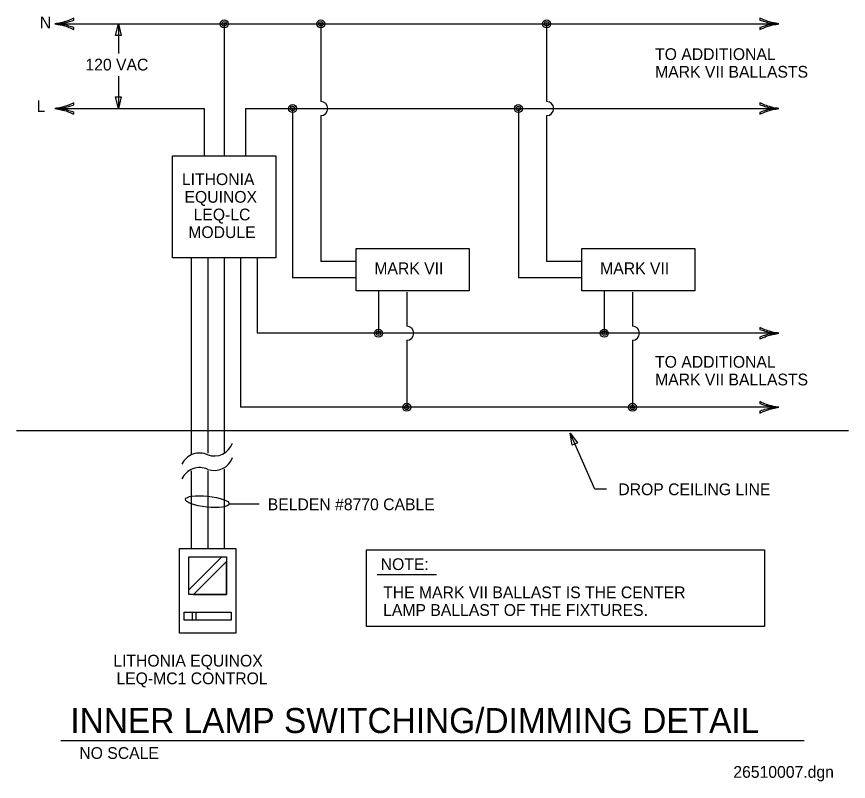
# Model space of a CAD drawing. Extents: x 10215.2 to 10262.3, y 10050.3 to 10093.6.
import ezdxf

# ---------------------------------------------------------------- set-up
doc = ezdxf.new("R2010")
doc.units = 0
for name, color, linetype in [('G-ANNO-TEXT', 7, 'Continuous'), ('G-DETL-OTLN', 7, 'Continuous'), ('Level 61', 7, 'Continuous')]:
    doc.layers.add(name, color=color, linetype=linetype)

msp = doc.modelspace()

# ---------------------------------------------------------------- linework, layer by layer
at = {"layer": 'G-ANNO-TEXT'}
for p, q in [((10220.937, 10093.182), (10220.937, 10091.493)), ((10220.937, 10090.216), (10220.937, 10088.382)), ((10247.945, 10066.804), (10246.539, 10069.988)), ((10248.612, 10066.804), (10247.945, 10066.804)), ((10227.223, 10065.974), (10228.928, 10065.974)), ((10235.608, 10061.97), (10238.975, 10061.97)), ((10217.675, 10052.56), (10259.814, 10052.56))]:
    msp.add_line(p, q, dxfattribs=at)
for points in [[(10220.77, 10092.515), (10220.937, 10093.182), (10221.103, 10092.515)], [(10221.103, 10089.048), (10220.937, 10088.382), (10220.77, 10089.048)], [(10246.656, 10069.311), (10246.539, 10069.988), (10246.961, 10069.445)], [(10235.008, 10063.37), (10257.557, 10063.37), (10257.557, 10059.023), (10235.008, 10059.023)]]:
    msp.add_lwpolyline(points, close=True, dxfattribs=at)
msp.add_ellipse((10225.98, 10066.106), major_axis=(1.243, -0.132), ratio=0.246355, dxfattribs=at)
at = {"layer": 'G-DETL-OTLN'}
for p, q in [((10217.337, 10093.182), (10258.385, 10093.182)), ((10226.937, 10093.182), (10226.937, 10085.706)), ((10232.414, 10093.182), (10232.414, 10088.782)), ((10245.214, 10093.182), (10245.214, 10088.782)), ((10217.337, 10088.382), (10225.803, 10088.382)), ((10225.803, 10088.382), (10225.803, 10085.706)), ((10228.137, 10088.382), (10258.385, 10088.382)), ((10228.137, 10088.382), (10228.137, 10085.706)), ((10230.814, 10088.382), (10230.814, 10078.782)), ((10243.614, 10088.382), (10243.614, 10078.782)), ((10232.414, 10087.982), (10232.414, 10079.715)), ((10245.214, 10087.982), (10245.214, 10079.715)), ((10225.07, 10079.924), (10225.07, 10068.818)), ((10226.003, 10079.924), (10226.003, 10068.86)), ((10226.937, 10079.924), (10226.937, 10068.86)), ((10227.87, 10079.924), (10227.87, 10071.45)), ((10228.803, 10079.924), (10228.803, 10075.648)), ((10234.414, 10079.715), (10232.414, 10079.715)), ((10247.214, 10079.715), (10245.214, 10079.715)), ((10234.414, 10078.782), (10230.814, 10078.782)), ((10247.214, 10078.782), (10243.614, 10078.782)), ((10235.681, 10078.048), (10235.681, 10075.648)), ((10237.281, 10077.982), (10237.281, 10076.048)), ((10248.481, 10078.048), (10248.481, 10075.648)), ((10250.081, 10077.982), (10250.081, 10076.048)), ((10258.385, 10075.648), (10228.803, 10075.648)), ((10237.281, 10075.248), (10237.281, 10071.45)), ((10250.081, 10075.248), (10250.081, 10071.45)), ((10258.385, 10071.45), (10227.87, 10071.45)), ((10225.07, 10067.848), (10225.07, 10063.448)), ((10226.003, 10067.848), (10226.003, 10063.448)), ((10226.937, 10067.943), (10226.937, 10063.448)), ((10224.937, 10061.115), (10224.937, 10062.982)), ((10224.937, 10062.982), (10226.803, 10062.982)), ((10227.07, 10060.848), (10227.07, 10062.715)), ((10225.203, 10060.848), (10227.07, 10060.848))]:
    msp.add_line(p, q, dxfattribs=at)
for points in [[(10217.337, 10093.182), (10217.431, 10093.166), (10217.524, 10093.151), (10217.645, 10093.132), (10217.77, 10093.098), (10217.877, 10093.07), (10217.97, 10093.044), (10218.047, 10093.014), (10218.132, 10092.982), (10218.21, 10092.951), (10218.29, 10092.919), (10218.361, 10092.886), (10218.417, 10092.858), (10218.417, 10092.966), (10218.348, 10092.991), (10218.281, 10093.015), (10218.209, 10093.036), (10218.138, 10093.057), (10218.05, 10093.081), (10217.981, 10093.102), (10217.885, 10093.119), (10217.804, 10093.134), (10217.711, 10093.15), (10217.625, 10093.161), (10217.546, 10093.167), (10217.482, 10093.172), (10217.417, 10093.177), (10217.337, 10093.182), (10217.437, 10093.188), (10217.537, 10093.196), (10217.666, 10093.206), (10217.785, 10093.226), (10217.873, 10093.242), (10217.964, 10093.258), (10218.05, 10093.281), (10218.161, 10093.313), (10218.239, 10093.335), (10218.321, 10093.362), (10218.417, 10093.398), (10218.417, 10093.506), (10218.345, 10093.471), (10218.241, 10093.423), (10218.162, 10093.394), (10218.06, 10093.354), (10217.957, 10093.316), (10217.871, 10093.292), (10217.764, 10093.263), (10217.685, 10093.241), (10217.599, 10093.225), (10217.513, 10093.21), (10217.425, 10093.196), (10217.337, 10093.182)], [(10217.337, 10093.182), (10217.431, 10093.166), (10217.524, 10093.151), (10217.645, 10093.132), (10217.77, 10093.098), (10217.877, 10093.07), (10217.97, 10093.044), (10218.047, 10093.014), (10218.132, 10092.982), (10218.21, 10092.951), (10218.29, 10092.919), (10218.361, 10092.886), (10218.417, 10092.858), (10218.417, 10092.966), (10218.348, 10092.991), (10218.281, 10093.015), (10218.209, 10093.036), (10218.138, 10093.057), (10218.05, 10093.081), (10217.981, 10093.102), (10217.885, 10093.119), (10217.804, 10093.134), (10217.711, 10093.15), (10217.625, 10093.161), (10217.546, 10093.167), (10217.482, 10093.172), (10217.417, 10093.177), (10217.337, 10093.182), (10217.437, 10093.188), (10217.537, 10093.196), (10217.666, 10093.206), (10217.785, 10093.226), (10217.873, 10093.242), (10217.964, 10093.258), (10218.05, 10093.281), (10218.161, 10093.313), (10218.239, 10093.335), (10218.321, 10093.362), (10218.417, 10093.398), (10218.417, 10093.506), (10218.345, 10093.471), (10218.241, 10093.423), (10218.162, 10093.394), (10218.06, 10093.354), (10217.957, 10093.316), (10217.871, 10093.292), (10217.764, 10093.263), (10217.685, 10093.241), (10217.599, 10093.225), (10217.513, 10093.21), (10217.425, 10093.196), (10217.337, 10093.182)], [(10258.385, 10093.182), (10258.291, 10093.198), (10258.198, 10093.212), (10258.076, 10093.231), (10257.951, 10093.265), (10257.844, 10093.294), (10257.751, 10093.319), (10257.675, 10093.35), (10257.59, 10093.382), (10257.511, 10093.412), (10257.431, 10093.444), (10257.361, 10093.478), (10257.305, 10093.505), (10257.305, 10093.398), (10257.374, 10093.372), (10257.441, 10093.348), (10257.513, 10093.327), (10257.583, 10093.306), (10257.671, 10093.282), (10257.74, 10093.262), (10257.836, 10093.244), (10257.918, 10093.23), (10258.011, 10093.214), (10258.097, 10093.202), (10258.175, 10093.196), (10258.239, 10093.191), (10258.305, 10093.186), (10258.385, 10093.182), (10258.284, 10093.175), (10258.185, 10093.167), (10258.055, 10093.158), (10257.937, 10093.137), (10257.849, 10093.121), (10257.758, 10093.105), (10257.671, 10093.082), (10257.561, 10093.05), (10257.483, 10093.028), (10257.401, 10093.001), (10257.305, 10092.966), (10257.305, 10092.857), (10257.377, 10092.892), (10257.481, 10092.94), (10257.559, 10092.969), (10257.662, 10093.009), (10257.764, 10093.047), (10257.851, 10093.071), (10257.958, 10093.1), (10258.036, 10093.122), (10258.123, 10093.138), (10258.209, 10093.153), (10258.297, 10093.167), (10258.385, 10093.182)], [(10217.337, 10088.382), (10217.431, 10088.366), (10217.524, 10088.351), (10217.645, 10088.332), (10217.77, 10088.298), (10217.877, 10088.27), (10217.97, 10088.244), (10218.047, 10088.214), (10218.132, 10088.182), (10218.21, 10088.151), (10218.29, 10088.119), (10218.361, 10088.086), (10218.417, 10088.058), (10218.417, 10088.166), (10218.348, 10088.191), (10218.281, 10088.215), (10218.209, 10088.236), (10218.138, 10088.257), (10218.05, 10088.281), (10217.981, 10088.302), (10217.885, 10088.319), (10217.804, 10088.334), (10217.711, 10088.35), (10217.625, 10088.361), (10217.546, 10088.367), (10217.482, 10088.372), (10217.417, 10088.377), (10217.337, 10088.382), (10217.437, 10088.388), (10217.537, 10088.396), (10217.666, 10088.406), (10217.785, 10088.426), (10217.873, 10088.442), (10217.964, 10088.458), (10218.05, 10088.481), (10218.161, 10088.513), (10218.239, 10088.535), (10218.321, 10088.562), (10218.417, 10088.598), (10218.417, 10088.706), (10218.345, 10088.671), (10218.241, 10088.623), (10218.162, 10088.594), (10218.06, 10088.554), (10217.957, 10088.516), (10217.871, 10088.492), (10217.764, 10088.463), (10217.685, 10088.441), (10217.599, 10088.425), (10217.513, 10088.41), (10217.425, 10088.396), (10217.337, 10088.382)], [(10217.337, 10088.382), (10217.431, 10088.366), (10217.524, 10088.351), (10217.645, 10088.332), (10217.77, 10088.298), (10217.877, 10088.27), (10217.97, 10088.244), (10218.047, 10088.214), (10218.132, 10088.182), (10218.21, 10088.151), (10218.29, 10088.119), (10218.361, 10088.086), (10218.417, 10088.058), (10218.417, 10088.166), (10218.348, 10088.191), (10218.281, 10088.215), (10218.209, 10088.236), (10218.138, 10088.257), (10218.05, 10088.281), (10217.981, 10088.302), (10217.885, 10088.319), (10217.804, 10088.334), (10217.711, 10088.35), (10217.625, 10088.361), (10217.546, 10088.367), (10217.482, 10088.372), (10217.417, 10088.377), (10217.337, 10088.382), (10217.437, 10088.388), (10217.537, 10088.396), (10217.666, 10088.406), (10217.785, 10088.426), (10217.873, 10088.442), (10217.964, 10088.458), (10218.05, 10088.481), (10218.161, 10088.513), (10218.239, 10088.535), (10218.321, 10088.562), (10218.417, 10088.598), (10218.417, 10088.706), (10218.345, 10088.671), (10218.241, 10088.623), (10218.162, 10088.594), (10218.06, 10088.554), (10217.957, 10088.516), (10217.871, 10088.492), (10217.764, 10088.463), (10217.685, 10088.441), (10217.599, 10088.425), (10217.513, 10088.41), (10217.425, 10088.396), (10217.337, 10088.382)], [(10258.385, 10088.382), (10258.291, 10088.398), (10258.198, 10088.412), (10258.076, 10088.431), (10257.951, 10088.465), (10257.844, 10088.494), (10257.751, 10088.519), (10257.675, 10088.55), (10257.59, 10088.582), (10257.511, 10088.612), (10257.431, 10088.644), (10257.361, 10088.678), (10257.305, 10088.705), (10257.305, 10088.598), (10257.374, 10088.572), (10257.441, 10088.548), (10257.513, 10088.527), (10257.583, 10088.506), (10257.671, 10088.482), (10257.74, 10088.462), (10257.836, 10088.444), (10257.918, 10088.43), (10258.011, 10088.414), (10258.097, 10088.402), (10258.175, 10088.396), (10258.239, 10088.391), (10258.305, 10088.386), (10258.385, 10088.382), (10258.284, 10088.375), (10258.185, 10088.367), (10258.055, 10088.358), (10257.937, 10088.337), (10257.849, 10088.321), (10257.758, 10088.305), (10257.671, 10088.282), (10257.561, 10088.25), (10257.483, 10088.228), (10257.401, 10088.201), (10257.305, 10088.166), (10257.305, 10088.057), (10257.377, 10088.092), (10257.481, 10088.14), (10257.559, 10088.169), (10257.662, 10088.209), (10257.764, 10088.247), (10257.851, 10088.271), (10257.958, 10088.3), (10258.036, 10088.322), (10258.123, 10088.338), (10258.209, 10088.353), (10258.297, 10088.367), (10258.385, 10088.382)], [(10258.385, 10075.648), (10258.291, 10075.664), (10258.198, 10075.679), (10258.076, 10075.698), (10257.951, 10075.731), (10257.844, 10075.76), (10257.751, 10075.786), (10257.675, 10075.816), (10257.59, 10075.848), (10257.511, 10075.879), (10257.431, 10075.911), (10257.361, 10075.944), (10257.305, 10075.971), (10257.305, 10075.864), (10257.374, 10075.839), (10257.441, 10075.815), (10257.513, 10075.794), (10257.583, 10075.773), (10257.671, 10075.749), (10257.74, 10075.728), (10257.836, 10075.711), (10257.918, 10075.696), (10258.011, 10075.68), (10258.097, 10075.669), (10258.175, 10075.663), (10258.239, 10075.658), (10258.305, 10075.653), (10258.385, 10075.648), (10258.284, 10075.642), (10258.185, 10075.634), (10258.055, 10075.624), (10257.937, 10075.603), (10257.849, 10075.587), (10257.758, 10075.571), (10257.671, 10075.549), (10257.561, 10075.517), (10257.483, 10075.495), (10257.401, 10075.467), (10257.305, 10075.432), (10257.305, 10075.323), (10257.377, 10075.359), (10257.481, 10075.407), (10257.559, 10075.435), (10257.662, 10075.475), (10257.764, 10075.514), (10257.851, 10075.538), (10257.958, 10075.567), (10258.036, 10075.589), (10258.123, 10075.605), (10258.209, 10075.619), (10258.297, 10075.634), (10258.385, 10075.648)], [(10258.385, 10075.648), (10258.291, 10075.664), (10258.198, 10075.679), (10258.076, 10075.698), (10257.951, 10075.731), (10257.844, 10075.76), (10257.751, 10075.786), (10257.675, 10075.816), (10257.59, 10075.848), (10257.511, 10075.879), (10257.431, 10075.911), (10257.361, 10075.944), (10257.305, 10075.971), (10257.305, 10075.864), (10257.374, 10075.839), (10257.441, 10075.815), (10257.513, 10075.794), (10257.583, 10075.773), (10257.671, 10075.749), (10257.74, 10075.728), (10257.836, 10075.711), (10257.918, 10075.696), (10258.011, 10075.68), (10258.097, 10075.669), (10258.175, 10075.663), (10258.239, 10075.658), (10258.305, 10075.653), (10258.385, 10075.648), (10258.284, 10075.642), (10258.185, 10075.634), (10258.055, 10075.624), (10257.937, 10075.603), (10257.849, 10075.587), (10257.758, 10075.571), (10257.671, 10075.549), (10257.561, 10075.517), (10257.483, 10075.495), (10257.401, 10075.467), (10257.305, 10075.432), (10257.305, 10075.323), (10257.377, 10075.359), (10257.481, 10075.407), (10257.559, 10075.435), (10257.662, 10075.475), (10257.764, 10075.514), (10257.851, 10075.538), (10257.958, 10075.567), (10258.036, 10075.589), (10258.123, 10075.605), (10258.209, 10075.619), (10258.297, 10075.634), (10258.385, 10075.648)], [(10258.385, 10071.45), (10258.291, 10071.466), (10258.198, 10071.481), (10258.076, 10071.5), (10257.951, 10071.533), (10257.844, 10071.562), (10257.751, 10071.588), (10257.675, 10071.618), (10257.59, 10071.65), (10257.511, 10071.681), (10257.431, 10071.713), (10257.361, 10071.746), (10257.305, 10071.773), (10257.305, 10071.666), (10257.374, 10071.641), (10257.441, 10071.617), (10257.513, 10071.596), (10257.583, 10071.575), (10257.671, 10071.551), (10257.74, 10071.53), (10257.836, 10071.513), (10257.918, 10071.498), (10258.011, 10071.482), (10258.097, 10071.471), (10258.175, 10071.465), (10258.239, 10071.46), (10258.305, 10071.455), (10258.385, 10071.45), (10258.284, 10071.444), (10258.185, 10071.436), (10258.055, 10071.426), (10257.937, 10071.405), (10257.849, 10071.389), (10257.758, 10071.373), (10257.671, 10071.351), (10257.561, 10071.319), (10257.483, 10071.297), (10257.401, 10071.269), (10257.305, 10071.234), (10257.305, 10071.125), (10257.377, 10071.161), (10257.481, 10071.209), (10257.559, 10071.237), (10257.662, 10071.277), (10257.764, 10071.316), (10257.851, 10071.34), (10257.958, 10071.369), (10258.036, 10071.391), (10258.123, 10071.407), (10258.209, 10071.421), (10258.297, 10071.436), (10258.385, 10071.45)]]:
    msp.add_lwpolyline(points, dxfattribs=at)
for points in [[(10224.012, 10085.706), (10229.861, 10085.706), (10229.861, 10079.924), (10224.012, 10079.924)], [(10234.414, 10080.448), (10240.814, 10080.448), (10240.814, 10078.048), (10234.414, 10078.048)], [(10247.214, 10080.448), (10253.614, 10080.448), (10253.614, 10078.048), (10247.214, 10078.048)], [(10224.403, 10063.448), (10227.603, 10063.448), (10227.603, 10058.648), (10224.403, 10058.648)], [(10224.937, 10062.982), (10227.07, 10062.982), (10227.07, 10060.848), (10224.937, 10060.848)], [(10224.67, 10059.848), (10227.337, 10059.848), (10227.337, 10059.382), (10224.67, 10059.382)]]:
    msp.add_lwpolyline(points, close=True, dxfattribs=at)
for centre, radius in [((10226.937, 10093.182), 0.226), ((10226.937, 10093.182), 0.127), ((10226.937, 10093.182), 0.0422), ((10232.414, 10093.182), 0.226), ((10232.414, 10093.182), 0.127), ((10232.414, 10093.182), 0.0422), ((10245.214, 10093.182), 0.226), ((10245.214, 10093.182), 0.127), ((10245.214, 10093.182), 0.0422), ((10230.814, 10088.382), 0.226), ((10230.814, 10088.382), 0.127), ((10230.814, 10088.382), 0.0422), ((10243.614, 10088.382), 0.226), ((10243.614, 10088.382), 0.127), ((10243.614, 10088.382), 0.0422), ((10235.681, 10075.648), 0.226), ((10235.681, 10075.648), 0.127), ((10235.681, 10075.648), 0.0422), ((10248.481, 10075.648), 0.226), ((10248.481, 10075.648), 0.127), ((10248.481, 10075.648), 0.0422), ((10237.281, 10071.45), 0.226), ((10237.281, 10071.45), 0.127), ((10237.281, 10071.45), 0.0422), ((10250.081, 10071.45), 0.226), ((10250.081, 10071.45), 0.127), ((10250.081, 10071.45), 0.0422)]:
    msp.add_circle(centre, radius, dxfattribs=at)
for centre in [(10232.414, 10088.382), (10245.214, 10088.382), (10237.281, 10075.648), (10250.081, 10075.648)]:
    msp.add_arc(centre, 0.4, 270, 90, dxfattribs=at)
at = {"layer": 'Level 61'}
for p, q in [((10262.317, 10070.117), (10215.171, 10070.117)), ((10224.937, 10061.115), (10226.803, 10062.982)), ((10226.803, 10062.982), (10224.937, 10061.115)), ((10225.203, 10060.848), (10227.07, 10062.715)), ((10227.07, 10062.715), (10225.203, 10060.848))]:
    msp.add_line(p, q, dxfattribs=at)
msp.add_lwpolyline([(10225.137, 10059.848), (10225.337, 10059.848), (10225.337, 10059.382), (10225.137, 10059.382)], close=True, dxfattribs=at)
for centre, radius, start, end in [((10226.37, 10069.79), 1.096, 250.4633, 340.4633), ((10225.537, 10067.757), 1.104, 64.9831, 154.9831), ((10226.37, 10068.965), 1.096, 250.4633, 340.4633), ((10225.537, 10066.932), 1.104, 64.9831, 154.9831)]:
    msp.add_arc(centre, radius, start, end, dxfattribs=at)

# ---------------------------------------------------------------- texts
at = {"layer": 'G-ANNO-TEXT'}
for s, height, p in [('N', 0.667, (10216.485, 10092.924)), ('TO ADDITIONAL', 0.66667, (10251.362, 10091.132)), ('120 VAC', 0.6667, (10219.07, 10090.539)), ('MARK VII BALLASTS', 0.66667, (10251.362, 10090.132)), ('L', 0.667, (10216.301, 10088.185)), ('LITHONIA', 0.6667, (10224.54, 10084.044)), ('EQUINOX', 0.6667, (10224.687, 10083.044)), ('LEQ-LC', 0.6667, (10225.201, 10082.044)), ('MODULE', 0.6667, (10224.902, 10081.044)), ('MARK VII', 0.6667, (10235.448, 10078.995)), ('MARK VII', 0.6667, (10248.248, 10078.995)), ('TO ADDITIONAL', 0.66667, (10251.362, 10073.693)), ('MARK VII BALLASTS', 0.66667, (10251.362, 10072.693)), ('DROP CEILING LINE', 0.66667, (10249.278, 10066.471)), ('BELDEN #8770 CABLE', 0.66667, (10229.407, 10065.618)), ('NOTE:', 0.6667, (10235.808, 10062.227)), ('THE MARK VII BALLAST IS THE CENTER', 0.66667, (10235.947, 10060.63)), ('LAMP BALLAST OF THE FIXTURES.', 0.66667, (10235.947, 10059.63)), ('LITHONIA EQUINOX', 0.66667, (10220.651, 10056.759)), ('LEQ-MC1 CONTROL', 0.66667, (10220.828, 10055.759)), ('INNER LAMP SWITCHING/DIMMING DETAIL', 1.41667, (10218.218, 10052.992)), ('NO SCALE', 0.6667, (10218.725, 10051.525)), ('26510007.dgn', 0.66667, (10255.796, 10050.453))]:
    msp.add_text(s, height=height, dxfattribs=at).set_placement(p)

doc.saveas('drawing.dxf')
